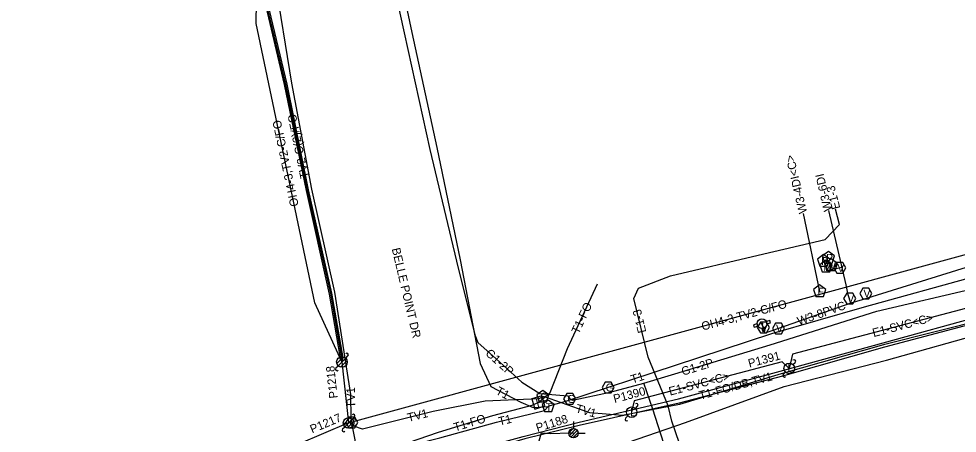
# Model space of a CAD drawing. Extents: x 2336688 to 2352634, y 362473 to 369571.
# Drawn here: x 2351041.3 to 2351485, y 368818 to 369013.7 of the extents above; entities that cross this region are included whole.
import ezdxf

# ---------------------------------------------------------------- set-up
doc = ezdxf.new("R2010")
doc.units = 0
for name, color, linetype in [('RD_EX_DV_Prop', 7, 'Continuous'), ('RD_EX_DV_TX_Prop', 7, 'Continuous'), ('RD_EX_RW', 7, 'Continuous'), ('RD_EX_RW_TX', 7, 'Continuous'), ('RD_HC_CL_Rel', 7, 'Continuous'), ('RD_HC_Data_Tic', 7, 'Continuous'), ('RD_PD_CstnLmt', 7, 'Continuous'), ('RD_PD_Final_TrvlWay', 7, 'Continuous'), ('RD_PD_PatLn2', 7, 'Continuous'), ('RD_PD_PatLn4', 7, 'Continuous'), ('RD_SHT_ShtClip', 7, 'Continuous'), ('RD_Sketch2', 7, 'Continuous'), ('RD_Sketch8', 7, 'Continuous'), ('RD_TX_Misc1', 7, 'Continuous')]:
    doc.layers.add(name, color=color, linetype=linetype)

msp = doc.modelspace()

# ---------------------------------------------------------------- linework, layer by layer
at = {"layer": 'RD_EX_RW_TX'}
for points in [[(2351168.22, 369289), (2351184.03, 369217.25), (2351194.44, 369162.64), (2351203.85, 369115.24), (2351215.71, 369060.82), (2351227.21, 369007.22), (2351238.98, 368952.88), (2351250.05, 368899.81), (2351259.46, 368850.86), (2351264.5, 368840.05), (2351278.6, 368832.56), (2351284.45, 368830.16), (2351291.64, 368830.61)], [(2351198.76, 368823.01), (2351198.52, 368824.9), (2351198.25, 368836.21), (2351190.72, 368884.6), (2351179.85, 368933.22), (2351170.45, 368983.31), (2351162.38, 369032.96), (2351153.33, 369082.81), (2351143.41, 369129.58), (2351133.6, 369178.86), (2351125.36, 369229.59), (2351112.81, 369278.13)], [(2351153.96, 369042.26), (2351155.5, 369041.02), (2351157.29, 369024.92), (2351167.43, 368982.74), (2351177.7, 368932.89), (2351188.7, 368884.02), (2351193.83, 368853.61), (2351194.09, 368851.6)], [(2351153.96, 369042.26), (2351155.83, 369041.26), (2351157.97, 369025.19), (2351167.98, 368982.78), (2351178.11, 368932.9), (2351189.2, 368884.08), (2351194.47, 368853.53), (2351194.09, 368851.6)], [(2351153.96, 369042.26), (2351155.09, 369040.85), (2351156.91, 369025.02), (2351166.81, 368982.76), (2351177.17, 368932.66), (2351188.08, 368883.71), (2351193.27, 368853.33), (2351194.09, 368851.6)], [(2351026.67, 368705.73), (2351072.69, 368726.31), (2351095.34, 368740.06), (2351116.22, 368749.97), (2351165.51, 368767.17), (2351212.21, 368781.21), (2351311.35, 368807.4), (2351356.55, 368822.99), (2351403.13, 368840.09), (2351451.54, 368852.43), (2351499.93, 368866.02), (2351548.68, 368876.43), (2351597.38, 368889.51), (2351644.05, 368904.92), (2351693.91, 368918.56), (2351742.3, 368929.46), (2351791.99, 368937.8), (2351833.59, 368947.12), (2351885, 368956.88), (2351939.56, 368969.89)], [(2351765.09, 368961.33), (2351762.65, 368958.7), (2351731.46, 368952.33), (2351690.92, 368936.8), (2351644.39, 368912.81), (2351617.15, 368901.31), (2351597.28, 368893.86), (2351548.04, 368883.26), (2351498.82, 368871.39), (2351450.63, 368858.65), (2351402.34, 368844.85), (2351353.62, 368832.17), (2351306.23, 368821.59), (2351280.49, 368815.25), (2351211.24, 368794.97), (2351186.06, 368787.7), (2351186.43, 368794.28), (2351186.89, 368796.09), (2351185.08, 368794.48), (2351153.67, 368786.02), (2351107.67, 368770.53), (2351057.77, 368748.3), (2351012.48, 368735.27)], [(2351011.06, 368741.96), (2351053.69, 368758.05), (2351107.39, 368776.15), (2351152.93, 368787.71), (2351184.57, 368795.27), (2351186.89, 368796.09), (2351188.61, 368798.02), (2351216.11, 368809.61), (2351240.4, 368815.83), (2351267.18, 368823.24), (2351289.83, 368828.63), (2351291.64, 368830.61), (2351292.6, 368830.98), (2351299.9, 368833.16), (2351351.82, 368850.12), (2351397.43, 368865.04), (2351441.13, 368877.68), (2351493.72, 368892.16)], [(2351216, 368810.33), (2351239.68, 368818.38), (2351265.48, 368826.27), (2351284.03, 368831.22), (2351286.93, 368832.5), (2351289.02, 368834.12), (2351292.56, 368837.12), (2351300.74, 368857.95), (2351314.96, 368888.53)], [(2351012.91, 368733.98), (2351058.97, 368746.67), (2351108.07, 368769.44), (2351156.12, 368783.52), (2351185.09, 368789.77), (2351211.25, 368797.72), (2351279.85, 368816.48), (2351306.31, 368823.22), (2351353.2, 368834.25), (2351401.27, 368847.29), (2351450, 368860.64), (2351498.06, 368873.82)], [(2351499.06, 368872), (2351450.2, 368859.78), (2351401.85, 368845.93), (2351353.7, 368831.58), (2351326.67, 368826.28), (2351311.23, 368827.61), (2351289.86, 368835.15), (2351289.09, 368835.13), (2351287.25, 368834.26), (2351261.79, 368833.03), (2351237.29, 368828.25), (2351212.6, 368822.12), (2351203.83, 368819.92), (2351199.75, 368821.32), (2351198.76, 368823.01), (2351199.15, 368820.41), (2351205.9, 368785.94), (2351223.8, 368694.72), (2351226.67, 368682.68), (2351226.54, 368679.35), (2351224.55, 368678.69), (2351202.58, 368675.7), (2351201.7, 368675.07)]]:
    msp.add_lwpolyline(points, dxfattribs=at)
for points in [[(2351289.09, 368838.13), (2351286.23, 368836.06), (2351287.32, 368832.71), (2351290.85, 368832.71), (2351291.94, 368836.06)], [(2351288.58, 368835.63), (2351283.8, 368834.15), (2351285.28, 368829.38), (2351290.06, 368830.85)], [(2351291.64, 368833.61), (2351288.79, 368831.54), (2351289.88, 368828.19), (2351293.4, 368828.19), (2351294.49, 368831.54)], [(2351201.65, 368823.01), (2351200.2, 368825.51), (2351197.32, 368825.51), (2351195.87, 368823.01), (2351197.32, 368820.51), (2351200.2, 368820.51)]]:
    msp.add_lwpolyline(points, close=True, dxfattribs=at)
at = {"layer": 'RD_HC_CL_Rel'}
for points in [[(2351211.87, 369060.2), (2351223.48, 369007.05), (2351235.68, 368951.97), (2351248.3, 368899.28), (2351256.86, 368864.38), (2351258.4, 368860.79), (2351267.06, 368853.06), (2351279.19, 368842.1), (2351287.59, 368836.67), (2351300.9, 368835.62), (2351301.79, 368834.14), (2351303.04, 368833.64), (2351320.88, 368837.27), (2351336.77, 368841.59), (2351351.45, 368846.05), (2351396.57, 368859.65), (2351447.03, 368875.53), (2351494.07, 368886.58), (2351543.46, 368901.18), (2351588.65, 368910.33), (2351641.69, 368920.56), (2351691.88, 368930.79), (2351740.06, 368940.33), (2351801.74, 368956.51)], [(2351370.43, 368735.99), (2351369.13, 368740.04), (2351364.33, 368757), (2351341.1, 368829.3), (2351336.77, 368841.59)]]:
    msp.add_lwpolyline(points, dxfattribs=at)
for points in [[(2351321.39, 368837.02), (2351322.84, 368839.52), (2351321.39, 368842.02), (2351318.51, 368842.02), (2351317.06, 368839.52), (2351318.51, 368837.02)], [(2351303.23, 368831.64), (2351304.68, 368834.14), (2351303.23, 368836.64), (2351300.35, 368836.64), (2351298.9, 368834.14), (2351300.35, 368831.64)]]:
    msp.add_lwpolyline(points, close=True, dxfattribs=at)
at = {"layer": 'RD_HC_Data_Tic'}
for p, q in [((2351195.86, 368853.37), (2351196.92, 368854.43)), ((2351191.68, 368850.96), (2351194.74, 368854.02)), ((2351192.32, 368849.84), (2351195.86, 368853.37)), ((2351193.44, 368849.19), (2351196.5, 368852.25)), ((2351407.35, 368850.35), (2351408.41, 368851.41)), ((2351191.26, 368848.78), (2351192.32, 368849.84)), ((2351402.76, 368845.75), (2351403.82, 368846.81)), ((2351332.84, 368829.64), (2351333.9, 368830.7)), ((2351194.79, 368822.13), (2351197.86, 368825.19)), ((2351195.44, 368821.01), (2351198.98, 368824.54)), ((2351196.56, 368820.36), (2351199.62, 368823.42)), ((2351198.98, 368824.54), (2351200.04, 368825.61)), ((2351303.57, 368823.45), (2351303.57, 368820.17)), ((2351328.24, 368825.04), (2351329.3, 368826.1)), ((2351194.38, 368819.95), (2351195.44, 368821.01)), ((2351301.36, 368818.08), (2351303.44, 368820.17)), ((2351301.61, 368816.92), (2351304.6, 368819.91)), ((2351302.27, 368816.16), (2351305.36, 368819.26)), ((2351303.27, 368815.76), (2351305.77, 368818.25)), ((2351305.79, 368817.96), (2351309.1, 368817.96))]:
    msp.add_line(p, q, dxfattribs=at)
for centre, radius in [((2351194.09, 368851.6), 2.5), ((2351405.59, 368848.58), 2.5), ((2351331.07, 368827.87), 2.5), ((2351197.21, 368822.78), 2.5), ((2351303.57, 368817.95), 2.22)]:
    msp.add_circle(centre, radius, dxfattribs=at)
for centre, start, end in [((2351196.39, 368854.96), 315, 135), ((2351407.88, 368851.94), 315, 135), ((2351191.79, 368848.25), 135, 315), ((2351403.29, 368845.22), 135, 315), ((2351333.37, 368831.23), 315, 135), ((2351199.51, 368826.14), 315, 135), ((2351328.77, 368824.51), 135, 315), ((2351194.91, 368819.42), 135, 315)]:
    msp.add_arc(centre, 0.75, start, end, dxfattribs=at)
at = {"layer": 'RD_PD_Final_TrvlWay'}
for points in [[(2351813.53, 369029.36), (2351821.49, 368992.14), (2351823.9, 368989.67), (2351794.62, 368950.67), (2351778.05, 368940.44), (2351775.15, 368938.78), (2351642.49, 368917.24), (2351514.5, 368883.56), (2351514.77, 368877.23), (2351511.62, 368882.8), (2351407.12, 368855.31), (2351405.59, 368848.58), (2351402.3, 368851.72), (2351332.34, 368833.32), (2351331.07, 368827.87)], [(2351380.9, 368735.05), (2351380.01, 368735.9), (2351374.68, 368748.33), (2351371.69, 368758.73), (2351362.67, 368786.92), (2351350.13, 368823.67), (2351348.41, 368830.89), (2351338.9, 368853.84), (2351332.14, 368881.62), (2351334.27, 368886.55), (2351349.44, 368892.24), (2351390.85, 368902), (2351422.65, 368909.4), (2351429.43, 368916.53), (2351427.53, 368923.8)]]:
    msp.add_lwpolyline(points, dxfattribs=at)
at = {"layer": 'RD_SHT_ShtClip'}
for p, q in [((2351197.21, 368822.78), (2351572.13, 368925.03)), ((2351194.09, 368851.6), (2351197.21, 368822.78)), ((2351197.21, 368822.78), (2350916.38, 368704.49))]:
    msp.add_line(p, q, dxfattribs=at)
msp.add_lwpolyline([(2351194.09, 368851.6), (2351181.3, 368879.57), (2351153.53, 369011.51), (2351153.96, 369042.26)], dxfattribs=at)
at = {"layer": 'RD_Sketch2'}
for p, q in [((2351412.18, 368921.74), (2351419.96, 368884.94)), ((2351390.4, 368869.6), (2351388.64, 368869.14)), ((2351388.64, 368869.14), (2351388.94, 368868.02)), ((2351388.94, 368868.02), (2351390.74, 368868.5)), ((2351396.45, 368871.22), (2351394.76, 368870.77)), ((2351395.01, 368869.64), (2351396.75, 368870.1)), ((2351396.75, 368870.1), (2351396.45, 368871.22)), ((2351392.67, 368867.4), (2351393.06, 368865.95)), ((2351393.06, 368865.95), (2351394.17, 368866.25)), ((2351394.17, 368866.25), (2351393.79, 368867.67))]:
    msp.add_line(p, q, dxfattribs=at)
for points in [[(2351829.3, 368956.12), (2351825.48, 368955.65), (2351796.45, 368952.27), (2351741.12, 368946.36), (2351687.12, 368939), (2351639.33, 368929.45), (2351588.67, 368920.67), (2351539, 368909.06), (2351489.27, 368896.27), (2351440.12, 368880.97), (2351434.75, 368879.34), (2351397.29, 368866.24), (2351394.12, 368865.24), (2351393.38, 368867.94), (2351392.71, 368869.71)], [(2351434.75, 368879.34), (2351433.52, 368883.28), (2351432.49, 368888.06), (2351424.28, 368923.09)], [(2351430.56, 368896.29), (2351423.38, 368894.6), (2351422.94, 368896.51)]]:
    msp.add_lwpolyline(points, dxfattribs=at)
for points in [[(2351424.14, 368903.84), (2351421.24, 368901.74), (2351422.34, 368898.33), (2351425.93, 368898.33), (2351427.04, 368901.74)], [(2351421.81, 368902.32), (2351418.9, 368900.22), (2351420.01, 368896.81), (2351423.6, 368896.81), (2351424.71, 368900.22)], [(2351422.92, 368899.68), (2351420.02, 368897.57), (2351421.13, 368894.16), (2351424.71, 368894.16), (2351425.82, 368897.57)], [(2351425.48, 368900.29), (2351422.58, 368898.18), (2351423.69, 368894.77), (2351427.27, 368894.77), (2351428.38, 368898.18)], [(2351432.4, 368896.04), (2351430.96, 368898.54), (2351428.07, 368898.54), (2351426.63, 368896.04), (2351428.07, 368893.54), (2351430.96, 368893.54)], [(2351419.96, 368887.99), (2351417.05, 368885.88), (2351418.16, 368882.47), (2351421.75, 368882.47), (2351422.86, 368885.88)], [(2351444.72, 368883.96), (2351443.28, 368886.46), (2351440.39, 368886.46), (2351438.95, 368883.96), (2351440.39, 368881.46), (2351443.28, 368881.46)], [(2351437.08, 368881.55), (2351435.64, 368884.04), (2351432.75, 368884.04), (2351431.31, 368881.55), (2351432.75, 368879.05), (2351435.64, 368879.05)], [(2351396.26, 368867.94), (2351394.82, 368870.44), (2351391.93, 368870.44), (2351390.49, 368867.94), (2351391.93, 368865.44), (2351394.82, 368865.44)], [(2351403.4, 368867.42), (2351401.96, 368869.92), (2351399.07, 368869.92), (2351397.63, 368867.42), (2351399.07, 368864.92), (2351401.96, 368864.92)]]:
    msp.add_lwpolyline(points, close=True, dxfattribs=at)
for radius in [2.31, 0.289]:
    msp.add_circle((2351392.71, 368869.71), radius, dxfattribs=at)
for start, end in [(182.61, 211.5863), (358.2637, 27.2401), (269.1706, 298.1378)]:
    msp.add_arc((2351392.71, 368869.71), 2.31, start, end, dxfattribs=at)
at = {"layer": 'RD_Sketch8'}
msp.add_lwpolyline([(2351303.57, 368817.95), (2351301.77, 368818), (2351292.47, 368817.64), (2351288.25, 368818.02), (2351286.36, 368811.48)], dxfattribs=at)

# ---------------------------------------------------------------- texts
at = {"layer": 'RD_EX_DV_Prop'}
for s, rotation, p in [('E1-3', 104.626, (2351429.77, 368924.3)), ('E1-3', 103.6713, (2351338.05, 368865.81)), ('E1-SVC<C>', 14.7421, (2351445.52, 368863.34)), ('E1-SVC<C>', 14.7421, (2351349.23, 368835.69))]:
    msp.add_text(s, height=4, rotation=rotation, dxfattribs=at).set_placement(p)
at = {"layer": 'RD_EX_DV_TX_Prop'}
for s, rotation, p in [('P1391', 14.7421, (2351386.74, 368848.92)), ('P1218', 96.1733, (2351192.11, 368834.59)), ('P1390', 14.7421, (2351323, 368832.16)), ('P1217', 22.841, (2351180, 368817.8)), ('P1188', 17.2813, (2351286.54, 368818.48))]:
    msp.add_text(s, height=4, rotation=rotation, dxfattribs=at).set_placement(p)
at = {"layer": 'RD_EX_RW'}
for s, rotation, p in [('TV2-C(2)/FO', 101.5487, (2351178.45, 368938.77)), ('T1-FO', 65.0726, (2351306.03, 368864.57)), ('T1', 18.0866, (2351331.44, 368841.36)), ('T1-FO/DB,TV1', 15.06, (2351363.53, 368833.77)), ('TV1', 91.3573, (2351200.4, 368829.98)), ('T1', 332.0242, (2351266.46, 368836.7)), ('TV1', 13.9395, (2351225.56, 368823.27)), ('TV1', 344.1983, (2351304.28, 368827.95)), ('T1-FO', 17.0066, (2351247.63, 368818.72)), ('T1', 13.4058, (2351268.61, 368821.52))]:
    msp.add_text(s, height=4, rotation=rotation, dxfattribs=at).set_placement(p)
at = {"layer": 'RD_EX_RW_TX'}
for s, height, p in [('C', 4, (2351287.86, 368833.13)), ('T', 3.75, (2351290.41, 368828.39)), ('C', 3.75, (2351197.61, 368821.13))]:
    msp.add_text(s, height=height, dxfattribs=at).set_placement(p)
msp.add_text('F', height=4, rotation=17.1718, dxfattribs=at).set_placement((2351286.44, 368830.26))
at = {"layer": 'RD_HC_CL_Rel'}
for p in [(2351318.8, 368837.64), (2351300.64, 368832.27)]:
    msp.add_text('G', height=3.75, dxfattribs=at).set_placement(p)
at = {"layer": 'RD_HC_Data_Tic'}
for p in [(2351404.77, 368846.65), (2351330.26, 368825.93)]:
    msp.add_text('L', height=4, rotation=360, dxfattribs=at).set_placement(p)
at = {"layer": 'RD_PD_CstnLmt'}
for s, rotation, p in [('W3-4DI<C>', 103.205, (2351414.11, 368922.23)), ('W3-6DI', 103.205, (2351425.89, 368923.25)), ('W3-8PVC', 19.2778, (2351410.2, 368868.84))]:
    msp.add_text(s, height=4, rotation=rotation, dxfattribs=at).set_placement(p)
at = {"layer": 'RD_PD_PatLn2'}
for rotation, p in [(317.8906, (2351261.62, 368855.24)), (16.7741, (2351355.27, 368845.11))]:
    msp.add_text('G1-2P', height=4, rotation=rotation, dxfattribs=at).set_placement(p)
at = {"layer": 'RD_PD_PatLn4'}
for rotation, p in [(101.8866, (2351173.68, 368925.45)), (15.2556, (2351364.69, 368866.38))]:
    msp.add_text('OH4-3,TV2-C/FO', height=4, rotation=rotation, dxfattribs=at).set_placement(p)
at = {"layer": 'RD_Sketch2'}
for p in [(2351420.65, 368897.4), (2351422.99, 368898.92)]:
    msp.add_text('P', height=3.75, rotation=360, dxfattribs=at).set_placement(p)
for s, p in [('M', (2351424.11, 368895.24)), ('M', (2351421.55, 368894.63)), ('V', (2351428.31, 368894.17)), ('F', (2351418.91, 368882.95)), ('V', (2351440.63, 368882.08)), ('V', (2351432.98, 368879.67)), ('V', (2351392.17, 368866.06)), ('V', (2351399.31, 368865.54))]:
    msp.add_text(s, height=3.75, dxfattribs=at).set_placement(p)
at = {"layer": 'RD_TX_Misc1'}
msp.add_text('BELLE POINT DR', height=4, rotation=283.3145, dxfattribs=at).set_placement((2351217.61, 368905.04))

doc.saveas('drawing.dxf')
